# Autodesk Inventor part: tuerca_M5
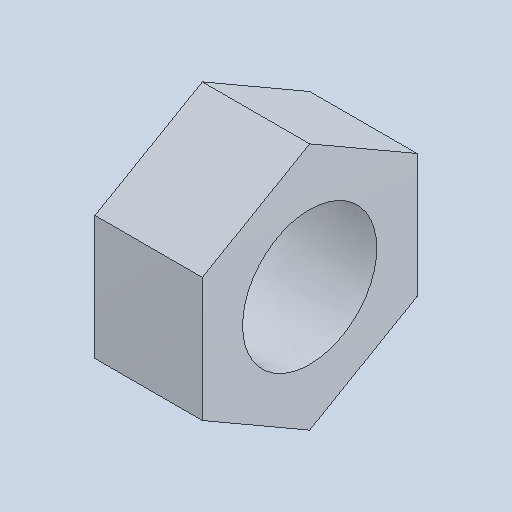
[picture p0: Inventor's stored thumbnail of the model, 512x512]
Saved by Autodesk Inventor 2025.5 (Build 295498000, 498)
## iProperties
Created: 2026-10
Part Number: tuerca_M5
Material: Genérico
Document SubType Name: Modeling
Designer: Luis M
Density: 1 g/cm^3
Appearance: Valor por defecto
Author: Luis M
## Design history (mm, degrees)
feature "Base1"
node "Sólido1"
